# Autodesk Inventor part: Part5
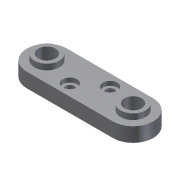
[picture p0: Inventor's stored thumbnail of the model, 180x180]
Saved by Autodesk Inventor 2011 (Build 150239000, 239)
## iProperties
Shininess: 77.0
Length Units: 11269
Angle Units: 11279
Time Units: 11290
Mass Units: 11283
Length Display Precision: 3
Angle Display Precision: 2
Created: 2002-01
Part Number: Part5
Document SubType Name: Modeling
Designer: ***
Density: 1 g/cm^3
Density: 0.0
Volumn: 0.0
Area: 0.0
PropertySet Name: Model Information
Control State: 0
Master: False
Checked Out: False
Author: ***
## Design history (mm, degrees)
sketch "Sketch1"
  geometry: L1 (-33.118, 12.346)-(26.882, 12.361); L2 (-33.111, -15.654)-(26.889, -15.639); C1 r 6 at (-33.114, -1.654); C2 r 6 at (26.886, -1.639); A1 r 14 centre (-33.114, -1.654) between (-33.118, 12.346) and (-33.111, -15.654); A2 r 14 centre (26.886, -1.639) between (26.889, -15.639) and (26.882, 12.361)
  constraints: 4 centre point, 4 end point, 4 point on circle, 4 tangent, 2 coincident, 2 equal radius
  dimensions: "d0" = 60 distance of L1.start L1.end; "d1" = 14 radius of A1; "d2" = 12 diameter of C1
extrude "Extrusion1" new body sketch "Sketch1" distance "d3" = 10; taper "d4" = 0 deg
sketch "Sketch2"
  geometry: C1 r 6 at (26.886, -1.639) reference; C2 r 6 at (-33.114, -1.654) reference; C3 r 8.694 at (-33.114, -1.654); C4 r 8.694 at (26.886, -1.639)
  constraints: 2 centre point, 2 coincident, 1 equal radius
extrude "Extrusion2" join sketch "Sketch2" distance "d5" = 4; taper "d6" = 0 deg
sketch "Sketch3"
  geometry: L1 (26.889, -15.639)-(-33.111, -15.654) reference; L2 (-33.118, 12.346)-(26.882, 12.361) reference; C1 r 6 at (-33.114, -1.654) reference; C2 r 6 at (26.886, -1.639) reference; 2 further points
  dimensions: "d14" = 8 distance from line of L1 point (-11.114, -7.649); "d15" = 22 horizontal distance of C1.centre point (-11.114, -7.649); "d16" = 8 distance from line of L2 point (4.886, 4.355); "d17" = 22 horizontal distance of C2.centre point (4.886, 4.355)
hole "Hole1" sketch "Sketch3" at (-11.114, -7.649), (4.886, 4.355) diameter "d7" = 6; stored, may be unused: countersink angle "d11" = 82 deg, drill point angle "d13" = 118 deg; dims "d8" = 6, "d9" = 10, "d10" = 3, "d12" = 8
body "Solid1"
